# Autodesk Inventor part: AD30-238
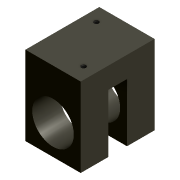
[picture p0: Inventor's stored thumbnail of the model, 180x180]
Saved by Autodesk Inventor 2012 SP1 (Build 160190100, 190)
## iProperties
Shininess: 0.0
Length Units: 11269
Angle Units: 11279
Time Units: 11290
Mass Units: 11283
Length Display Precision: 3
Angle Display Precision: 2
Compacted: True
Created: 2000-06
Part Number: AD30-238
Project: BONDING PRESS
Description: BEARING MOUNT
Document SubType Name: Modeling
Designer: Ron
Density: 1 g/cm^3
Material: Default
Density: 0.0
Volumn: 0.0
Area: 0.0
PropertySet Name: Model Information
Control State: 0
Master: False
Checked Out: False
Title: BEARING MOUNT
Author: Ron
Revision Number: A
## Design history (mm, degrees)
node "Extrusion1" dims "d4" = 50.8, "d5" = 0
  sketch "Sketch1"
    geometry: L1 (19, 34)-(-19, 34); L2 (-19, 34)-(-19, -20.424); L3 (-19, -20.424)-(19, -20.424); L4 (19, -20.424)-(19, 34); L5 (0, -20.424)-(0, 0); C1 r 14.287 at (0, 0); 1 further point
    constraints: 10 end point, 3 parallel, 2 coincident, 1 centre point, 1 horizontal, 1 midpoint, 1 perpendicular
    dimensions: "d0" = 28.575 diameter of C1; "d2" = 34 distance from line of L1 L5.end; "d3" = 38 distance of L2.end L3.end; "d21" = 54.42368 distance of L1.end L2.end
node "Extrusion2" dims "d8" = 9.525, "d9" = 0
  sketch "Sketch2"
    geometry: L1 (0, 0)-(-50.8, 0) reference; L2 (-31.85, 40)-(-18.95, 40); L3 (-18.95, 40)-(-18.95, 0); L4 (-18.95, 0)-(-31.85, 0); L5 (-31.85, 0)-(-31.85, 40); 1 further point
    constraints: 8 end point, 2 midpoint, 2 parallel, 1 horizontal, 1 perpendicular
    dimensions: "d6" = 12.9 distance between parallel lines of L3 L5; "d7" = 40 distance between parallel lines of L2 L1
node "Hole1" dims "d14" = 3.242, "d15" = 4, "d16" = 2, "d17" = 60 deg, "d18" = 12, "d19" = 118 deg, "d20" = 8
  sketch "Sketch3"
    geometry: L1 (0, -50.8)-(38, -50.8) reference; L2 (38, 0)-(38, -50.8) reference; L3 (38, 0)-(0, 0) reference; L4 (0, 0)-(0, -50.8) reference; 2 further points
    dimensions: "d10" = 10 distance from line of L1 point (30, -40.8); "d11" = 10 distance from line of L3 point (8, -10); "d12" = 8 distance from line of L2 point (30, -40.8); "d13" = 8 distance from line of L4 point (8, -10) (= d12)
body "Solid1"
